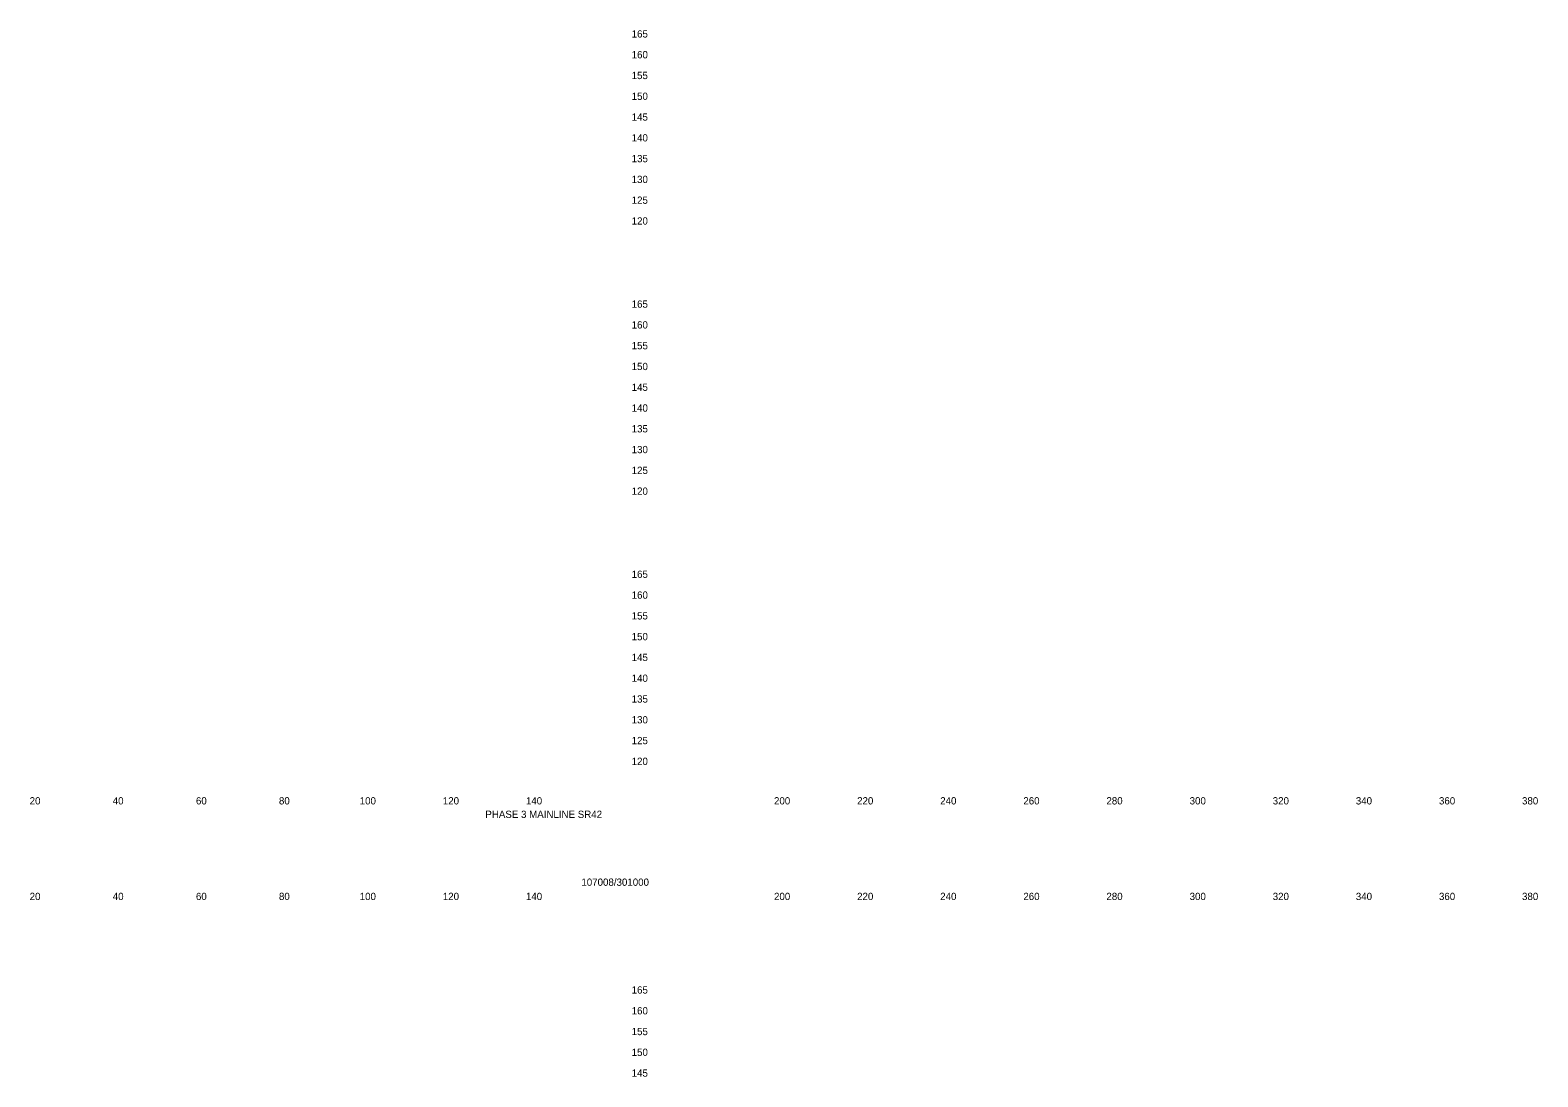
# Model space of a CAD drawing. Extents: x 21281 to 22024, y 6472 to 15198.
# Drawn here: x 21661.4 to 22024.2, y 7559.8 to 7811.6 of the extents above; entities that cross this region are included whole.
import ezdxf

# ---------------------------------------------------------------- set-up
doc = ezdxf.new("R2010")
doc.units = 0
doc.layers.add('Draft_XS_Grid', color=7, linetype='Continuous')
doc.layers.add('Draft_XS_Text', color=7, linetype='Continuous')

msp = doc.modelspace()

# ---------------------------------------------------------------- texts
at = {"layer": 'Draft_XS_Grid'}
for s, p in [('  165  ', (21804.84, 7809.84)), ('  160  ', (21804.84, 7804.84)), ('  155  ', (21804.84, 7799.84)), ('  150  ', (21804.84, 7794.84)), ('  145  ', (21804.84, 7789.84)), ('  140  ', (21804.84, 7784.84)), ('  135  ', (21804.84, 7779.84)), ('  130  ', (21804.84, 7774.84)), ('  125  ', (21804.84, 7769.84)), ('  120  ', (21804.84, 7764.84)), ('  165  ', (21804.84, 7744.84)), ('  160  ', (21804.84, 7739.84)), ('  155  ', (21804.84, 7734.84)), ('  150  ', (21804.84, 7729.84)), ('  145  ', (21804.84, 7724.84)), ('  140  ', (21804.84, 7719.84)), ('  135  ', (21804.84, 7714.84)), ('  130  ', (21804.84, 7709.84)), ('  125  ', (21804.84, 7704.84)), ('  120  ', (21804.84, 7699.84)), ('  165  ', (21804.84, 7679.84)), ('  160  ', (21804.84, 7674.84)), ('  155  ', (21804.84, 7669.84)), ('  150  ', (21804.84, 7664.84)), ('  145  ', (21804.84, 7659.84)), ('  140  ', (21804.84, 7654.84)), ('  135  ', (21804.84, 7649.84)), ('  130  ', (21804.84, 7644.84)), ('  125  ', (21804.84, 7639.84)), ('  120  ', (21804.84, 7634.84)), ('  165  ', (21804.84, 7579.84)), ('  160  ', (21804.84, 7574.84)), ('  155  ', (21804.84, 7569.84)), ('  150  ', (21804.84, 7564.84)), ('  145  ', (21804.84, 7559.84))]:
    msp.add_text(s, height=1.75, dxfattribs=at).set_placement(p)
at = {"layer": 'Draft_XS_Text'}
for s, p in [('  20  ', (21659.95, 7625.34)), ('  40  ', (21679.95, 7625.34)), ('  60  ', (21699.97, 7625.34)), ('  80  ', (21719.95, 7625.34)), ('  100  ', (21739.39, 7625.34)), ('  120  ', (21759.39, 7625.34)), ('  140  ', (21779.39, 7625.34)), ('  200  ', (21839.1, 7625.34)), ('  220  ', (21859.1, 7625.34)), ('  240  ', (21879.1, 7625.34)), ('  260  ', (21899.11, 7625.34)), ('  280  ', (21919.1, 7625.34)), ('  300  ', (21939.13, 7625.34)), ('  320  ', (21959.13, 7625.34)), ('  340  ', (21979.13, 7625.34)), ('  360  ', (21999.14, 7625.34)), ('  380  ', (22019.13, 7625.34)), ('PHASE 3 MAINLINE SR42', (21770.93, 7622.09)), ('107008/301000', (21794.04, 7605.77)), ('  20  ', (21659.95, 7602.34)), ('  40  ', (21679.95, 7602.34)), ('  60  ', (21699.97, 7602.34)), ('  80  ', (21719.95, 7602.34)), ('  100  ', (21739.39, 7602.34)), ('  120  ', (21759.39, 7602.34)), ('  140  ', (21779.39, 7602.34)), ('  200  ', (21839.1, 7602.34)), ('  220  ', (21859.1, 7602.34)), ('  240  ', (21879.1, 7602.34)), ('  260  ', (21899.11, 7602.34)), ('  280  ', (21919.1, 7602.34)), ('  300  ', (21939.13, 7602.34)), ('  320  ', (21959.13, 7602.34)), ('  340  ', (21979.13, 7602.34)), ('  360  ', (21999.14, 7602.34)), ('  380  ', (22019.13, 7602.34))]:
    msp.add_text(s, height=1.75, dxfattribs=at).set_placement(p)

doc.saveas('drawing.dxf')
